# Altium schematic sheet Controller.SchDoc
size A4; SheetNumber: 2; SheetTotal: 2
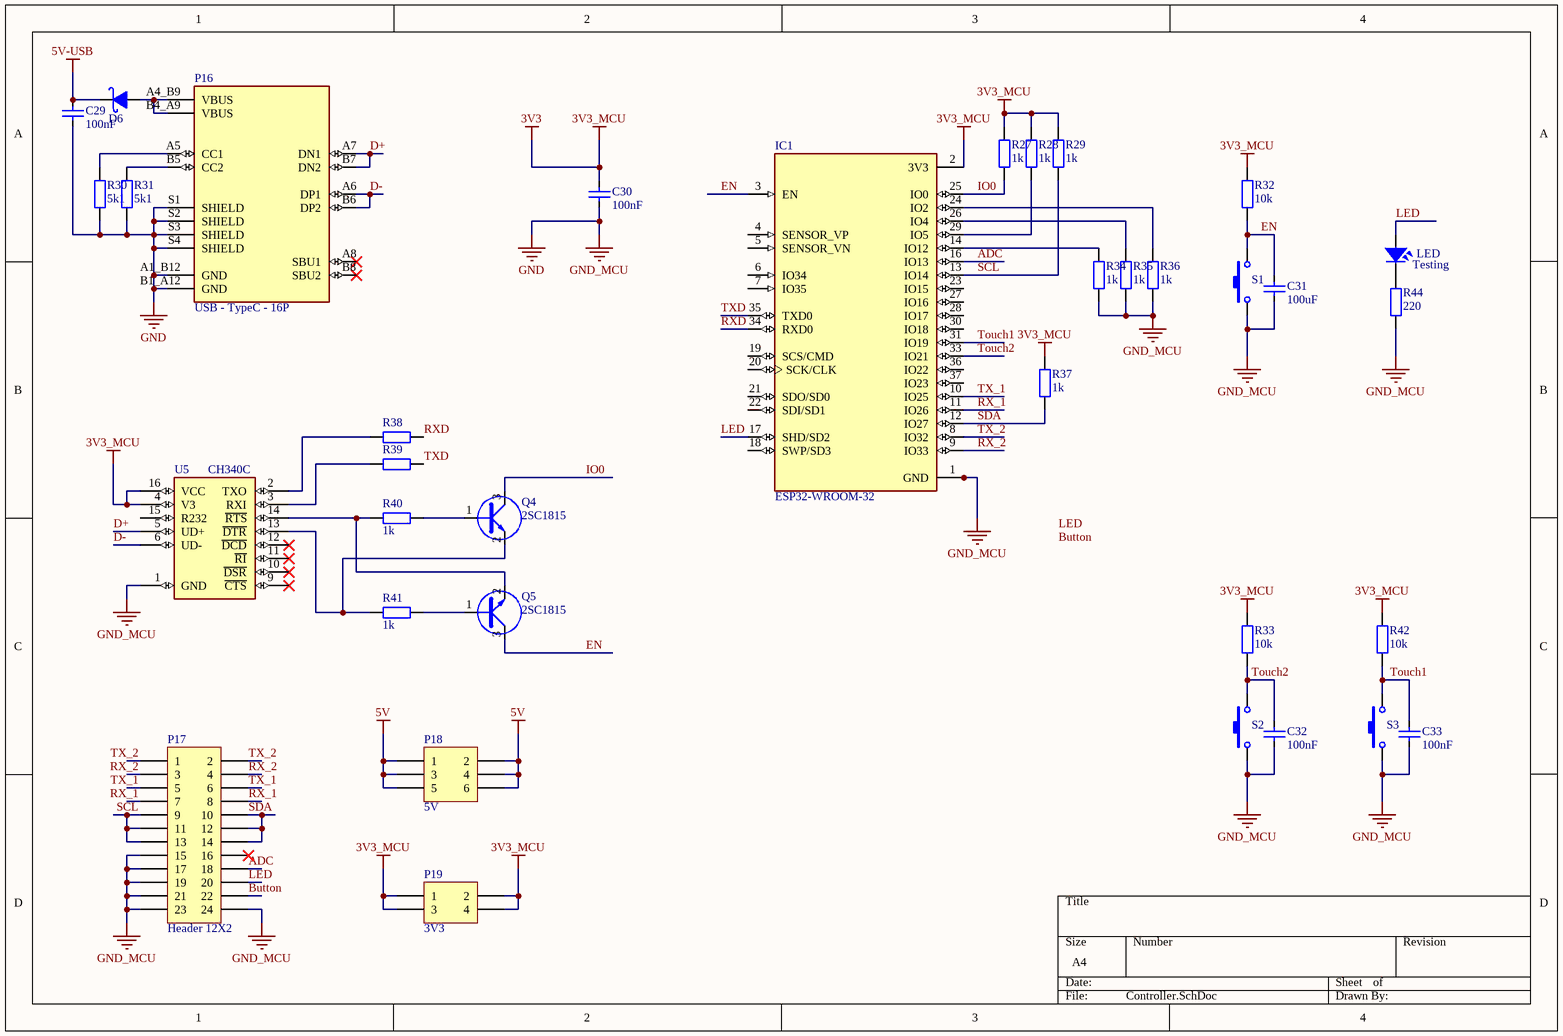
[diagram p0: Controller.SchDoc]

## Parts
C29  100nF  [CAP_0805]
C30  100nF  [CAP_0805]
C31  100uF  [CAP_0805]
C32  100nF  [CAP_0805]
C33  100nF  [CAP_0805]
D6  Diode Schottky  [DIO-214AA(SMB)]  (value not drawn)
IC1  ESP32-WROOM-32  [MODULE_ESP32-WROOM-32]
LED  Testing  [LED-0805-Blue]
P16  USB - TypeC - 16P  [USB C 16P]
P17  Header 12X2  [HDR2X12]  (no BOM)
P18  5V  [HDR2X3]  (no BOM)
P19  3V3  [HDR2X2]  (no BOM)
Q4  2SC1815  [SOT23D]
Q5  2SC1815  [SOT23D]
R27  1k  [RES-SMD-0805]
R28  1k  [RES-SMD-0805]
R29  1k  [RES-SMD-0805]
R30  5k1  [RES-SMD-0805]
R31  5k1  [RES-SMD-0805]
R32  10k  [RES-SMD-0805]
R33  10k  [RES-SMD-0805]
R34  1k  [RES-SMD-0805]
R35  1k  [RES-SMD-0805]
R36  1k  [RES-SMD-0805]
R37  1k  [RES-SMD-0805]
R38  0R  [RES-SMD-0805]  (value not drawn)
R39  0R  [RES-SMD-0805]  (value not drawn)
R40  1k  [RES-SMD-0805]
R41  1k  [RES-SMD-0805]
R42  10k  [RES-SMD-0805]
R44  220  [RES-SMD-0805]
S1  SW-SMD  [SW 3x2x4]  (value not drawn)
S2  SW-SMD  [SW 3x2x4]  (value not drawn)
S3  SW-SMD  [SW 3x2x4]  (value not drawn)
U5  CH340C  [SOP-16]

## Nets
3V3: C30.2 IC1.2(3V3) P19.1 P19.2 P19.3 P19.4 R27.1 R28.1 R29.1 R32.1 R33.1 R37.1 R42.1 U5.4(V3) U5.16(VCC)  [also labelled 3V3_MCU]
5V: P18.1 P18.2 P18.3 P18.4 P18.5 P18.6
5V-USB: C29.2 D6.2(K)
GND: C29.1 C30.1 C31.1 C32.1 C33.1 IC1.1(GND) IC1.15(GND) IC1.38(GND) IC1.39_1(GND) IC1.39_2(GND) IC1.39_3(GND) IC1.39_4(GND) IC1.39_5(GND) IC1.39_6(GND) IC1.39_7(GND) IC1.39_8(GND) IC1.39_9(GND) IC1.39_10(GND) IC1.39_11(GND) IC1.39_12(GND) IC1.39_13(GND) IC1.39_14(GND) IC1.39_15(GND) IC1.39_16(GND) IC1.39_17(GND) IC1.39_18(GND) IC1.39_19(GND) IC1.39_20(GND) IC1.39_21(GND) P16.A1_B12(GND) P16.B1_A12(GND) P16.S1(SHIELD) P16.S2(SHIELD) P16.S3(SHIELD) P16.S4(SHIELD) P17.15 P17.17 P17.19 P17.21 P17.23 P17.24 R30.2 R31.2 R34.2 R35.2 R36.1 R44.2 S1.1 S2.1 S3.1 U5.1(GND)  [also labelled GND_MCU]
ADC: IC1.16(IO13) P17.18
Button: P17.22
D+: P16.A7(DN1) P16.B7(DN2) U5.5(UD+)
D-: P16.A6(DP1) P16.B6(DP2) U5.6(UD-)
EN: C31.2 IC1.3(EN) Q5.3(C) R32.2 S1.2
IO0: IC1.25(IO0) Q4.3(C) R27.2
LED: IC1.17(SHD/SD2) LED.1 P17.20
RX_1: IC1.11(IO26) P17.7 P17.8
RX_2: IC1.9(IO33) P17.3 P17.4
RXD: IC1.34(RXD0) R38.1
SCL: IC1.13(IO14) P17.9 P17.11 P17.13 R29.2
SDA: IC1.12(IO27) P17.10 P17.12 P17.14 R37.2
Touch1: C33.2 IC1.31(IO19) R42.2 S3.2
Touch2: C32.2 IC1.33(IO21) R33.2 S2.2
TX_1: IC1.10(IO25) P17.5 P17.6
TX_2: IC1.8(IO32) P17.1 P17.2
TXD: IC1.35(TXD0) R39.1
NetD6_1: D6.1(A) P16.A4_B9(VBUS) P16.B4_A9(VBUS)
NetIC1_14: IC1.14(IO12) R34.1
NetIC1_24: IC1.24(IO2) R36.2
NetIC1_26: IC1.26(IO4) R35.1
NetIC1_29: IC1.29(IO5) R28.2
NetLED_2: LED.2 R44.1
NetP16_A5: P16.A5(CC1) R30.1
NetP16_B5: P16.B5(CC2) R31.1
NetQ4_1: Q4.1(B) R40.1
NetQ4_2: Q4.2(E) R41.2 U5.13(~{DTR})
NetQ5_1: Q5.1(B) R41.1
NetQ5_2: Q5.2(E) R40.2 U5.14(~{RTS})
NetR38_2: R38.2 U5.2(TXO)
NetR39_2: R39.2 U5.3(RXI)

Not connected (* = marked no-connect by the designer): IC1 4(SENSOR_VP) 5(SENSOR_VN) 6(IO34) 7(IO35) 18(SWP/SD3) 19(SCS/CMD) 20(SCK/CLK) 21(SDO/SD0) 22(SDI/SD1) 23(IO15) 27(IO16) 28(IO17) 30(IO18) 36(IO22) 37(IO23); P16 A8(SBU1)* B8(SBU2)*; P17 16*; U5 9(~{CTS})* 10(~{DSR})* 11(~{RI})* 12(~{DCD})* 15(R232)

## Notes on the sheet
- Labels drawn without touching a wire or pin: Button, LED

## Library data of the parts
C29-C33 = CapSMD: C 0805; Value: 33p
D6 = Diode Schottky: SS54
IC1 = ESP32-WROOM-32: Bluetooth, WiFi Transceiver Module 2.4GHz ~ 2.5GHz Surface Mount; MF: Espressif Systems
LED = LED: LED Single colour Green and Red; Value: LED 3 ly Single Colour
P17 = Header 12X2: Header, 12-Pin, Dual row
P18 = Header 3X2: Header, 3-Pin, Dual row
P19 = Header 2X2: Header, 2-Pin, Dual row
Q4 Q5 = C1815: NPN 600mW, ECB; Value: C1815
R27-R42 R44 = Resistor - SMD: R 0805; Manufacturer: Generic Components; Class: Passive
S1-S3 = SW-SMD: Switch
U5 = CH340C: USB to serial chip CH340; MF: WCH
